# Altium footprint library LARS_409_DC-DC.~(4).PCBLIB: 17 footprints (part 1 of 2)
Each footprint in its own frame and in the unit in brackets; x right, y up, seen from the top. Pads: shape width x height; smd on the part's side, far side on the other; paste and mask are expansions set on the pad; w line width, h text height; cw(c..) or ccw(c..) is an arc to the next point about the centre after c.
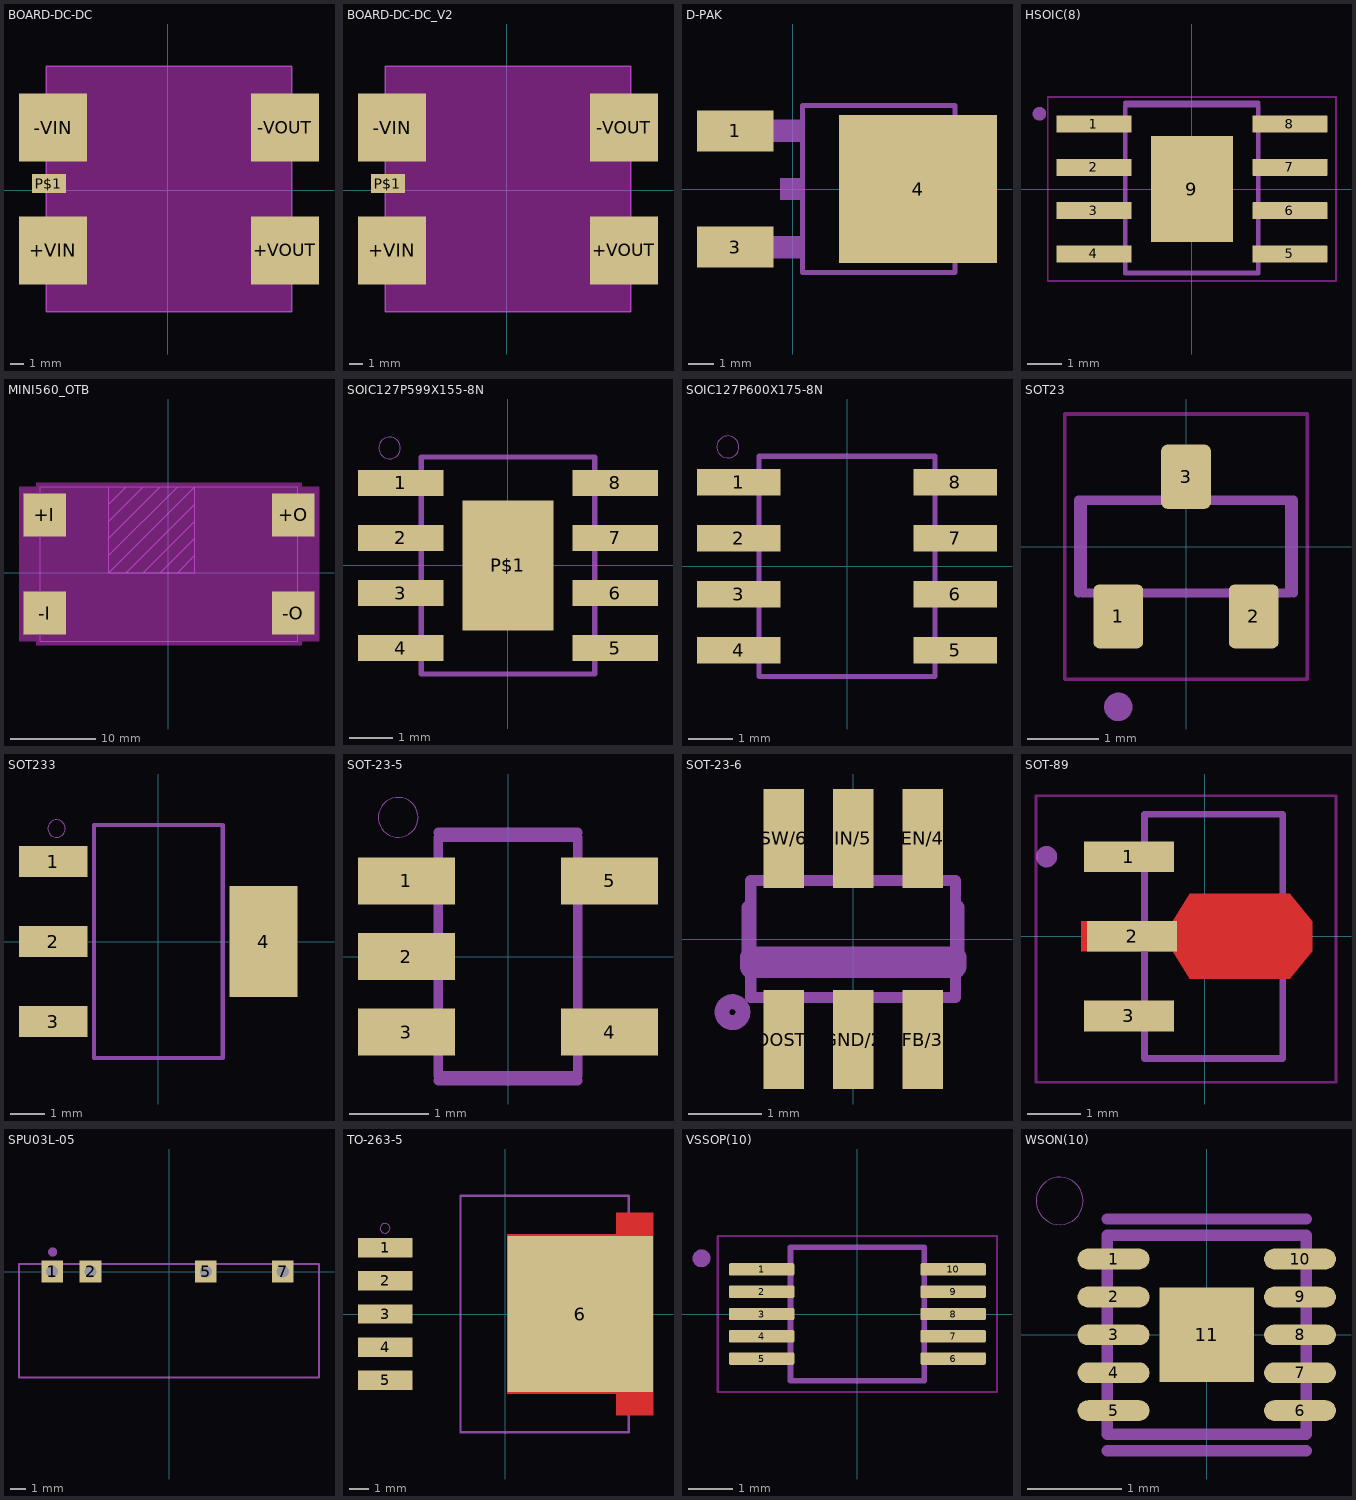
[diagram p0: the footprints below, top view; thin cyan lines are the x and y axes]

## BOARD-DC-DC [mm]
pads (5):
  rect 5x5 smd: +VIN(-8.39,-4.39) +VOUT(8.61,-4.39) -VIN(-8.39,4.61) -VOUT(8.61,4.61)
  rect 2.5x1.4 smd: P$1(-8.7,0.5)
Top keep-out:
  region: -8.89,-8.89 -8.89,9.11 9.11,9.11 9.11,-8.89
tPlace:
  lines w0.127: -8.89,-8.89 -8.89,9.11 9.11,9.11 9.11,-8.89 -8.89,-8.89

## BOARD-DC-DC_V2 [mm]
pads (5):
  rect 5x5 smd: +VIN(-8.39,-4.39) +VOUT(8.61,-4.39) -VIN(-8.39,4.61) -VOUT(8.61,4.61)
  rect 2.5x1.4 smd: P$1(-8.7,0.5)
Top keep-out:
  region: -8.89,-8.89 -8.89,9.11 9.11,9.11 9.11,-8.89
tPlace:
  lines w0.127: -8.89,-8.89 -8.89,9.11 9.11,9.11 9.11,-8.89 -8.89,-8.89

## D-PAK [mm]
pads (3):
  rect 3x1.6 smd: 1(-2.26,2.28) 3(-2.26,-2.28)
  rect 6.2x5.8 smd: 4(4.92,0)
tDocu:
  region: -2.616,2.718 0.279,2.718 0.279,1.854 -2.616,1.854
  region: -2.616,-1.854 0.279,-1.854 0.279,-2.718 -2.616,-2.718
  region: 6.477,2.565 7.188,2.565 7.645,2.108 7.645,-2.108 7.188,-2.565 6.477,-2.565
  lines w0.203: 6.375,-3.277 6.375,3.277 ; 6.477,-2.565 7.188,-2.565 7.645,-2.108 7.645,2.108 7.188,2.565 6.477,2.565 6.477,-2.565
tPlace:
  region: -0.483,0.432 0.279,0.432 0.279,-0.432 -0.483,-0.432
  lines w0.203: 6.375,-3.277 0.381,-3.277 0.381,3.277 6.375,3.277

## HSOIC(8) [mm]
pads (9):
  rect 2.2x0.5 smd: 1(-2.875,1.905) 2(-2.875,0.635) 3(-2.875,-0.635) 4(-2.875,-1.905)
  rrect10% 2.2x0.5 smd: 5(2.875,-1.905) 6(2.875,-0.635) 7(2.875,0.635) 8(2.875,1.905)
  rect 2.4x3.1 smd: 9(0,0)
Top keep-out:
  lines w0.05: -4.225,-2.7 -4.225,2.7 4.225,2.7 4.225,-2.7 -4.225,-2.7
tDocu:
  circle w0.2: c-4.47,2.205 r0.1
  lines w0.127: -1.95,-2.45 -1.95,2.45 1.95,2.45 1.95,-2.45 -1.95,-2.45
tPlace:
  circle w0.2: c-4.47,2.205 r0.1
  lines w0.127: -1.95,-2.475 1.95,-2.475 ; -1.95,2.525 1.95,2.525

## MINI560_OTB [mm]
pads (4):
  rect 5x5 smd: +I(-14.44,6.76) +O(14.56,6.76) -I(-14.44,-4.7) -O(14.56,-4.7)
Top keep-out:
  region: -15.44,10.53 15.56,10.53 15.56,10.03 17.56,10.03 17.56,-7.97 15.56,-7.97 15.56,-8.47 -15.44,-8.47 -15.44,-7.97 -17.44,-7.97 -17.44,10.03 -15.44,10.03
tPlace:
  lines w0.127: -6.94,0.03 3.06,10.03 ; -6.94,0.03 -6.94,2.03 ; -6.94,0.03 -4.94,0.03 ; -6.94,2.03 1.06,10.03 ; -6.94,2.03 -6.94,4.03 ; -6.94,4.03 -0.94,10.03 ; -6.94,4.03 -6.94,6.03 ; -6.94,6.03 -2.94,10.03 ; -6.94,6.03 -6.94,8.03 ; -6.94,8.03 -4.94,10.03 ; -6.94,8.03 -6.94,10.03 ; -6.94,10.03 -4.94,10.03 ; -6.94,10.03 -14.94,10.03 -14.94,-7.97 15.06,-7.97 15.06,10.03 3.06,10.03 ; -4.94,0.03 3.06,8.03 ; -4.94,0.03 -2.94,0.03 ; -4.94,10.03 -2.94,10.03 ; -2.94,0.03 3.06,6.03 ; -2.94,0.03 -0.94,0.03 ; -2.94,10.03 -0.94,10.03 ; -0.94,0.03 3.06,4.03 ; -0.94,0.03 1.06,0.03 ; -0.94,10.03 1.06,10.03 ; 1.06,0.03 3.06,2.03 ; 1.06,0.03 3.06,0.03 3.06,2.03 ; 1.06,10.03 3.06,10.03 ; 3.06,2.03 3.06,4.03 ; 3.06,4.03 3.06,6.03 ; 3.06,6.03 3.06,8.03 ; 3.06,8.03 3.06,10.03

## SOIC127P599X155-8N [mm]
pads (9):
  rect 1.972x0.602 smd: 1(-2.472,1.905) 2(-2.472,0.635) 3(-2.472,-0.635) 4(-2.472,-1.905) 5(2.472,-1.905) 6(2.472,-0.635) 7(2.472,0.635) 8(2.472,1.905)
  rect 2.1x3 smd: P$1(0,0)
tDocu:
  lines w0.12: -2,-2.5 -2,2.5 2,2.5 2,-2.5 -2,-2.5
tPlace:
  circle w0: c-2.729,2.71 r0.25
  lines w0.12: -2,-2.46 -2,-2.5 2,-2.5 2,-2.46 ; -2,2.46 -2,2.5 2,2.5 2,2.46

## SOIC127P600X175-8N [mm]
pads (8):
  rect 1.901x0.602 smd: 1(-2.455,1.905) 2(-2.455,0.635) 3(-2.455,-0.635) 4(-2.455,-1.905) 5(2.455,-1.905) 6(2.455,-0.635) 7(2.455,0.635) 8(2.455,1.905)
tDocu:
  lines w0.12: -2,-2.5 -2,2.5 2,2.5 2,-2.5 -2,-2.5
tPlace:
  circle w0: c-2.703,2.71 r0.25
  lines w0.12: -2,-2.46 -2,-2.5 2,-2.5 2,-2.46 ; -2,2.46 -2,2.5 2,2.5 2,2.46

## SOT23 [mm]
pads (3):
  rrect25% 0.7x0.9 smd: 1(-0.95,-0.98) 2(0.95,-0.98) 3(0,0.98)
Top keep-out:
  lines w0.05: -1.7,-1.86 1.7,-1.86 1.7,1.86 -1.7,1.86 -1.7,-1.86
tDocu:
  circle w0.2: c-0.95,-2.25 r0.1
  lines w0.127: -1.45,-0.65 1.45,-0.65 1.45,0.65 -1.45,0.65 -1.45,-0.65
tPlace:
  circle w0.2: c-0.95,-2.25 r0.1
  lines w0.127: -1.509,-0.65 -1.509,0.65 -0.61,0.65 ; 0.61,0.65 1.509,0.65 1.509,-0.65

## SOT233 [mil]
pads (4):
  rect 77.37x35 smd: 1(-119,90.55) 2(-119,0) 3(-119,-90.55)
  rect 77.37x125.56 smd: 4(119,0)
tDocu:
  lines w4.72: -72.83,-131.89 72.83,-131.89 72.83,131.89 -72.83,131.89 -72.83,-131.89
tPlace:
  circle w0: c-115.26,127.9 r9.84
  lines w4.72: -72.83,-118.06 -72.83,-131.89 72.83,-131.89 72.83,-72.78 ; -72.83,118.06 -72.83,131.89 72.83,131.89 72.83,72.78

## SOT-23-5 [mm]
pads (5):
  rect 1.217x0.589 smd: 1(-1.277,0.95) 2(-1.277,0) 3(-1.277,-0.95) 4(1.277,-0.95) 5(1.277,0.95)
tDocu:
  lines w0.12: -0.875,-1.5 -0.875,1.5 0.875,1.5 0.875,-1.5 -0.875,-1.5
tPlace:
  circle w0: c-1.38,1.749 r0.25
  lines w0.12: -0.875,-1.559 0.875,-1.559 ; -0.875,1.559 0.875,1.559
3D body "32-5.step": height 1.18, standoff 0.01, extent -1.42,-1.459 1.405,1.441

## SOT-23-6 [mm]
pads (6):
  rect 0.55x1.35 smd: BOOST/1(-0.95,-1.375) EN/4(0.95,1.375) FB/3(0.95,-1.375) GND/2(0,-1.375) IN/5(0,1.375) SW/6(-0.95,1.375)
tDocu:
  region: -1.2,-1.5 -1.2,-0.85 -0.7,-0.85 -0.7,-1.5
  region: -0.25,-1.5 -0.25,-0.85 0.25,-0.85 0.25,-1.5
  region: 0.7,-1.5 0.7,-0.85 1.2,-0.85 1.2,-1.5
  region: 0.7,0.85 0.7,1.5 1.2,1.5 1.2,0.85
  region: -1.2,0.85 -1.2,1.5 -0.7,1.5 -0.7,0.85
  region: -0.25,0.85 -0.25,1.5 0.25,1.5 0.25,0.85
  lines w0.152: -1.4,-0.8 1.4,-0.8 1.4,0.8 -1.4,0.8 -1.4,-0.8
tPlace:
  circle w0.203: c-1.65,-1 r0.144
  lines w0.203: -1.422,-0.43 -1.422,0.43 ; 1.422,-0.43 1.422,0.43
  lines w0.305: -1.397,-0.381 -1.397,-0.254 1.397,-0.254 1.397,-0.381 -1.397,-0.381
3D body "23-6.step": height 1.09, standoff 0, extent -1.385,-1.253 1.409,1.173

## SOT-89 [mm]
pads (3):
  rect 1.7x0.58 smd: 1(-1.425,1.5) 3(-1.425,-1.5)
  rect 1.7x0.58 smd mask+0: 2(-1.365,0)
Top:
  region: -2.325,0.28 -2.325,-0.28 -0.6,-0.28 -0.28,-0.8 1.605,-0.8 2.025,-0.28 2.025,0.28 1.605,0.8 -0.28,0.8 -0.6,0.28
Top keep-out:
  lines w0.05: -3.175,-2.75 2.475,-2.75 2.475,2.65 -3.175,2.65 -3.175,-2.75
Top Paste:
  region: -0.098,-0.38 -0.098,0.38 1.623,0.38 1.623,-0.38
Top Solder:
  region: -2.425,0.38 -2.425,-0.38 -0.6,-0.38 -0.28,-0.9 1.605,-0.9 2.125,-0.28 2.125,0.28 1.605,0.9 -0.28,0.9 -0.6,0.38
tDocu:
  circle w0.2: c-2.975,1.5 r0.1
  lines w0.127: -1.13,-2.3 1.47,-2.3 1.47,2.3 -1.13,2.3 -1.13,-2.3
tPlace:
  circle w0.2: c-2.975,1.5 r0.1
  lines w0.127: -1.13,-2.3 1.47,-2.3 1.47,-0.92 ; -1.13,2.3 1.47,2.3 1.47,0.92

## SPU03L-05 [mil]
pads (4):
  rect 56x56 / inner round 51.74 / far side rect 56x56 hole 31.5: 1(-303.94,0) 2(-203.94,0) 5(95.67,0) 7(295.67,0)
tDocu:
  circle w16: c-302.36,50.79 r3.94
tPlace:
  lines w6: -389.76,-275.59 -389.76,19.69 389.76,19.69 389.76,-275.59 -389.76,-275.59

## TO-263-5 [mil]
pads (6):
  rect 109.91x39.33 smd: 1(-243.5,133.86) 2(-243.5,66.93) 3(-243.5,0) 4(-243.5,-66.93) 5(-243.5,-133.86)
  rect 294.56x314.96 smd paste+0 mask+0: 6(151.18,0)
Top:
  region: 299.21,-204.72 299.21,204.72 224.41,204.72 224.41,161.42 3.94,161.42 3.94,-161.42 15.75,-161.42 224.41,-161.42 224.41,-204.72
Top Paste:
  region: 3.94,-157.48 3.94,157.48 224.41,157.48 224.41,204.72 299.21,204.72 299.21,-204.72 224.41,-204.72 224.41,-157.48
Top Solder:
  region: 3.94,-157.48 3.94,157.48 224.41,157.48 224.41,204.72 299.21,204.72 299.21,-204.72 224.41,-204.72 224.41,-157.48 212.6,-157.48
tDocu:
  lines w4.72: -90.94,-239.37 249.21,-239.37 249.21,239.37 -90.94,239.37 -90.94,-239.37
tPlace:
  circle w0: c-243.5,173.37 r9.84
  lines w4.72: 249.21,-213.38 249.21,-239.37 -90.94,-239.37 -90.94,239.37 249.21,239.37 249.21,213.38

## VSSOP(10) [mm]
pads (10):
  rrect25% 1.47x0.28 smd: 1(-2.15,1) 2(-2.15,0.5) 3(-2.15,0) 4(-2.15,-0.5) 5(-2.15,-1) 6(2.15,-1) 7(2.15,-0.5) 8(2.15,0) 9(2.15,0.5) 10(2.15,1)
Top keep-out:
  lines w0.05: -3.135,-1.75 3.135,-1.75 3.135,1.75 -3.135,1.75 -3.135,-1.75
tDocu:
  circle w0.2: c-3.5,1.25 r0.1
  lines w0.127: -1.5,-1.5 1.5,-1.5 1.5,1.5 -1.5,1.5 -1.5,-1.5
tPlace:
  circle w0.2: c-3.5,1.25 r0.1
  lines w0.127: -1.5,-1.5 1.5,-1.5 ; -1.5,1.5 1.5,1.5

## WSON(10) [mil]
pads (11):
  rrect100% 29.92x8.66 smd: 1(-38.76,31.5) 2(-38.76,15.75) 3(-38.76,0) 4(-38.76,-15.75) 5(-38.76,-31.5) 6(38.76,-31.5) 7(38.76,-15.75) 8(38.76,0) 9(38.76,15.75) 10(38.76,31.5)
  rect 39.37x39.37 smd: 11(0,0)
tDocu:
  lines w4.72: -41.34,-41.34 41.34,-41.34 41.34,41.34 -41.34,41.34 -41.34,-41.34
tPlace:
  circle w0: c-61.18,55.67 r9.84
  lines w4.72: -41.34,-48.19 41.34,-48.19 ; -41.34,48.19 41.34,48.19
